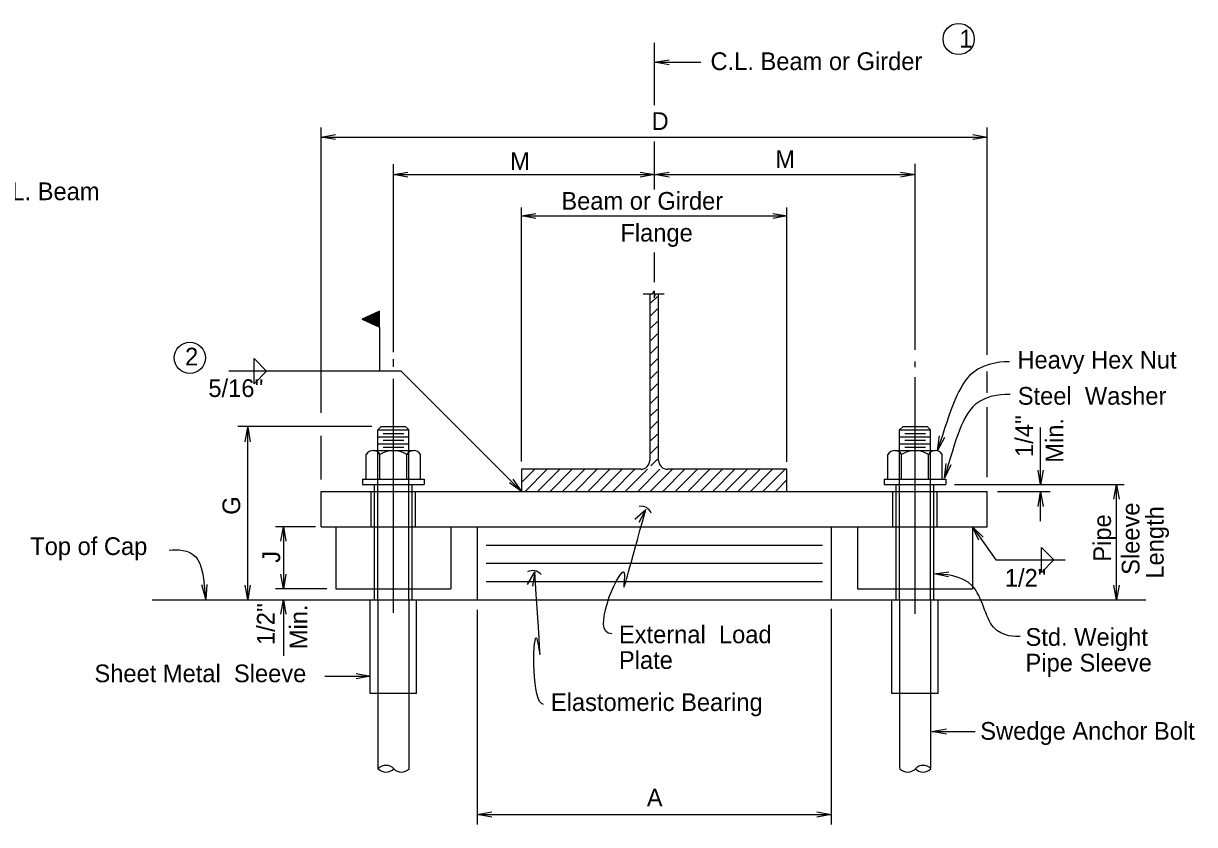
# Model space of a CAD drawing. Extents: x 113 to 232, y -103 to -27.
# Drawn here: x 123.95 to 129.46, y -71.71 to -67.93 of the extents above; entities that cross this region are included whole.
import ezdxf

# ---------------------------------------------------------------- set-up
doc = ezdxf.new("R2010")
doc.units = 0
doc.layers.add('1', color=7, linetype='Continuous')
doc.layers.add('B_Dimension', color=7, linetype='Continuous')

msp = doc.modelspace()

# ---------------------------------------------------------------- linework, layer by layer
at = {"layer": '1'}
for p, q in [((126.9201, -68.3191), (126.9201, -68.0268)), ((126.9201, -68.118), (127.1374, -68.118)), ((125.35, -69.7675), (125.35, -68.4251)), ((125.35, -68.4698), (128.4859, -68.4698)), ((128.4859, -69.4948), (128.4859, -68.4251)), ((126.9201, -68.717), (126.9201, -68.49)), ((125.69, -69.4816), (125.69, -68.5975)), ((128.1459, -69.4709), (128.1459, -68.5966)), ((125.69, -68.6466), (126.9201, -68.6466)), ((126.9201, -68.6466), (128.1459, -68.6466)), ((126.2929, -69.9965), (126.2929, -68.8018)), ((127.5429, -69.9989), (127.5429, -68.8018)), ((126.2929, -68.8413), (127.5444, -68.8413)), ((126.9201, -69.1529), (126.9201, -69.0125)), ((126.9098, -69.2073), (126.9177, -69.1932)), ((126.9177, -69.1932), (126.9177, -69.2263)), ((126.8663, -69.2073), (126.9098, -69.2073)), ((126.8972, -69.2073), (126.8972, -69.9915)), ((126.9177, -69.2263), (126.9239, -69.2073)), ((126.9239, -69.2073), (126.9642, -69.2073)), ((126.9387, -69.9915), (126.9387, -69.2073)), ((125.6244, -69.2896), (125.5434, -69.3274)), ((125.6244, -69.2896), (125.6244, -69.289)), ((125.6244, -69.365), (125.6244, -69.2896)), ((125.5434, -69.3274), (125.6244, -69.365)), ((125.6244, -69.365), (125.6244, -69.3955)), ((125.6244, -69.3955), (125.6244, -69.5718)), ((125.0345, -69.6308), (125.0345, -69.5128)), ((125.0345, -69.5128), (125.0935, -69.5718)), ((125.69, -69.5517), (125.69, -69.5157)), ((125.7274, -69.5718), (124.9152, -69.5718)), ((125.0935, -69.5718), (125.0345, -69.6308)), ((126.2929, -70.1374), (125.7274, -69.5718)), ((128.1459, -69.5532), (128.1459, -69.5258)), ((128.4859, -69.6732), (128.4859, -69.5735)), ((125.69, -70.7095), (125.69, -69.6072)), ((128.1459, -70.7145), (128.1459, -69.6003)), ((128.4859, -70.07), (128.4859, -69.7415)), ((125.5894, -69.832), (124.9581, -69.832)), ((125.0042, -70.6479), (125.0042, -69.8355)), ((125.6334, -69.832), (125.6171, -69.8483)), ((125.6171, -69.9455), (125.6171, -69.8483)), ((125.6171, -69.8483), (125.7629, -69.8483)), ((125.6334, -69.832), (125.7466, -69.832)), ((125.7466, -69.832), (125.7629, -69.8483)), ((125.7629, -69.9455), (125.7629, -69.8483)), ((128.073, -69.8483), (128.0893, -69.832)), ((128.073, -69.8483), (128.2188, -69.8483)), ((128.073, -69.9455), (128.073, -69.8483)), ((128.073, -69.8483), (128.2188, -69.8483)), ((128.0893, -69.832), (128.2025, -69.832)), ((128.2025, -69.832), (128.2188, -69.8483)), ((128.2188, -69.9455), (128.2188, -69.8483)), ((128.7372, -70.1065), (128.7372, -69.8375)), ((125.35, -70.0819), (125.35, -69.8759)), ((125.6171, -69.8807), (125.7629, -69.8807)), ((125.6414, -69.8646), (125.7386, -69.8646)), ((125.6414, -69.897), (125.7386, -69.897)), ((128.073, -69.8807), (128.2188, -69.8807)), ((128.0973, -69.8646), (128.1945, -69.8646)), ((128.0973, -69.897), (128.1945, -69.897)), ((125.5626, -70.0793), (125.5626, -69.9638)), ((125.5947, -69.9455), (125.7855, -69.9455)), ((125.6171, -69.913), (125.7629, -69.913)), ((125.6171, -70.6479), (125.6171, -69.9455)), ((125.627, -70.0793), (125.627, -69.9638)), ((125.6414, -69.9294), (125.7386, -69.9294)), ((125.7531, -70.0793), (125.7531, -69.9638)), ((125.7629, -70.6479), (125.7629, -69.9455)), ((125.8177, -70.0793), (125.8177, -69.9638)), ((128.0186, -70.0793), (128.0186, -69.9638)), ((128.0507, -69.9455), (128.2414, -69.9455)), ((128.073, -69.913), (128.2188, -69.913)), ((128.073, -70.6479), (128.073, -69.9455)), ((128.0829, -70.0793), (128.0829, -69.9638)), ((128.0973, -69.9294), (128.1945, -69.9294)), ((128.2091, -70.0793), (128.2091, -69.9638)), ((128.2188, -70.6479), (128.2188, -69.9455)), ((128.2737, -70.0793), (128.2737, -69.9638)), ((126.8555, -70.0332), (126.2929, -70.0332)), ((126.2929, -70.0332), (126.2929, -70.1374)), ((127.5429, -70.0332), (126.9804, -70.0332)), ((127.5429, -70.1374), (127.5429, -70.0332)), ((125.5441, -70.0793), (125.8358, -70.0793)), ((125.5441, -70.0793), (125.5441, -70.1053)), ((125.5441, -70.1053), (125.8358, -70.1053)), ((125.6015, -70.1386), (125.6015, -70.1056)), ((125.7785, -70.1386), (125.7785, -70.1056)), ((125.8358, -70.0793), (125.8358, -70.1053)), ((128.0001, -70.0793), (128.2917, -70.0793)), ((128.0001, -70.0793), (128.0001, -70.1053)), ((128.0001, -70.1053), (128.2917, -70.1053)), ((128.0574, -70.1382), (128.0574, -70.1049)), ((128.2344, -70.1382), (128.2344, -70.1059)), ((128.2917, -70.0793), (128.2917, -70.1053)), ((128.3317, -70.1053), (129.1305, -70.1053)), ((129.0945, -70.6479), (129.0945, -70.1053)), ((125.35, -70.304), (125.35, -70.1374)), ((125.35, -70.1374), (128.4859, -70.1374)), ((125.5859, -70.304), (125.5859, -70.1386)), ((125.6015, -70.304), (125.6015, -70.1386)), ((125.7785, -70.3039), (125.7785, -70.1386)), ((125.7941, -70.304), (125.7941, -70.1386)), ((128.0418, -70.305), (128.0418, -70.1382)), ((128.0574, -70.305), (128.0574, -70.1382)), ((128.2344, -70.306), (128.2344, -70.1412)), ((128.25, -70.306), (128.25, -70.1412)), ((128.4859, -70.304), (128.4859, -70.1374)), ((128.5338, -70.1374), (128.7828, -70.1374)), ((128.7372, -70.2774), (128.7372, -70.1398)), ((125.3235, -70.304), (125.1359, -70.304)), ((125.1721, -70.304), (125.1721, -70.5957)), ((125.35, -70.304), (128.4859, -70.304)), ((125.4192, -70.304), (125.4192, -70.5957)), ((125.6015, -70.5957), (125.6015, -70.304)), ((125.7785, -70.5957), (125.7785, -70.3039)), ((125.9608, -70.304), (125.9608, -70.5957)), ((126.0846, -70.304), (126.0846, -70.6479)), ((127.7513, -70.304), (127.7513, -70.6479)), ((127.8751, -70.304), (127.8751, -70.5957)), ((128.0574, -70.5957), (128.0574, -70.305)), ((128.2344, -70.5957), (128.2344, -70.306)), ((128.4167, -70.304), (128.4167, -70.5957)), ((128.4167, -70.304), (128.5267, -70.46)), ((126.1263, -70.39), (127.7096, -70.39)), ((128.7408, -70.519), (128.7408, -70.401)), ((128.7408, -70.401), (128.7998, -70.46)), ((128.5267, -70.46), (128.8531, -70.46)), ((128.7998, -70.46), (128.7408, -70.519)), ((126.1263, -70.476), (127.7096, -70.476)), ((126.1263, -70.562), (127.7096, -70.562)), ((125.3775, -70.5957), (125.1359, -70.5957)), ((125.4192, -70.5957), (125.9608, -70.5957)), ((125.6015, -70.6479), (125.6015, -70.5957)), ((125.7785, -70.6479), (125.7785, -70.5957)), ((127.8751, -70.5957), (128.4168, -70.5957)), ((128.0574, -70.6479), (128.0574, -70.5957)), ((128.2344, -70.6479), (128.2344, -70.5957)), ((124.5543, -70.6479), (129.2325, -70.6479)), ((125.1721, -70.6479), (125.1721, -70.9116)), ((125.5815, -71.0881), (125.5815, -70.6479)), ((125.6171, -70.6479), (125.6171, -71.0881)), ((125.7629, -70.6479), (125.7629, -71.0881)), ((125.7985, -71.0881), (125.7985, -70.6479)), ((128.0374, -71.0881), (128.0374, -70.6479)), ((128.073, -70.6479), (128.073, -71.0881)), ((128.2188, -70.6479), (128.2188, -71.0881)), ((128.2544, -71.0881), (128.2544, -70.6479)), ((126.0846, -70.6954), (126.0846, -71.7058)), ((127.7513, -70.6909), (127.7513, -71.7058)), ((125.3671, -71.0074), (125.583, -71.0074)), ((125.7985, -71.0881), (125.5815, -71.0881)), ((125.6171, -71.0881), (125.6171, -71.4447)), ((125.7629, -71.0881), (125.7629, -71.4445)), ((128.2544, -71.0881), (128.0374, -71.0881)), ((128.073, -71.0881), (128.073, -71.4412)), ((128.2188, -71.0881), (128.2188, -71.4414)), ((128.2257, -71.2679), (128.4284, -71.2679)), ((126.0846, -71.6581), (127.7513, -71.6581))]:
    msp.add_line(p, q, dxfattribs=at)
for points in [[(126.9024, -69.2507), (126.9335, -69.2195)], [(125.5961, -69.3519), (125.5961, -69.3029)], [(125.6003, -69.3538), (125.6003, -69.3009)], [(125.6046, -69.3558), (125.6046, -69.2989)], [(125.6089, -69.3578), (125.6089, -69.2969)], [(125.6132, -69.3599), (125.6132, -69.295)], [(125.6176, -69.3619), (125.6176, -69.2929)], [(125.6218, -69.3638), (125.6218, -69.2909)], [(126.9024, -69.3096), (126.9335, -69.2785)], [(125.5444, -69.3278), (125.5444, -69.327)], [(125.5486, -69.3299), (125.5486, -69.325)], [(125.553, -69.3319), (125.553, -69.323)], [(125.5573, -69.3338), (125.5573, -69.321)], [(125.5616, -69.3358), (125.5616, -69.319)], [(125.5659, -69.3378), (125.5659, -69.317)], [(125.5702, -69.3399), (125.5702, -69.315)], [(125.5745, -69.3419), (125.5745, -69.313)], [(125.5788, -69.3438), (125.5788, -69.311)], [(125.5831, -69.3458), (125.5831, -69.309)], [(125.5874, -69.3478), (125.5874, -69.307)], [(125.5917, -69.3499), (125.5917, -69.305)], [(126.9024, -69.3685), (126.9335, -69.3374)], [(126.9024, -69.4275), (126.9335, -69.3963)], [(126.9024, -69.4864), (126.9335, -69.4552)], [(126.9024, -69.5453), (126.9335, -69.5141)], [(126.9024, -69.6042), (126.9335, -69.573)], [(126.9024, -69.6631), (126.9335, -69.632)], [(126.9024, -69.722), (126.9335, -69.6909)], [(126.9024, -69.781), (126.9335, -69.7498)], [(126.9024, -69.8399), (126.9335, -69.8087)], [(126.9024, -69.8988), (126.9335, -69.8676)], [(126.9024, -69.9577), (126.9335, -69.9265)], [(126.9024, -70.0166), (126.9335, -69.9855)], [(126.2929, -70.0958), (126.3555, -70.0332)], [(126.2929, -70.0369), (126.2966, -70.0332)], [(126.3103, -70.1374), (126.4144, -70.0332)], [(126.3692, -70.1374), (126.4734, -70.0332)], [(126.4281, -70.1374), (126.5323, -70.0332)], [(126.487, -70.1374), (126.5912, -70.0332)], [(126.5459, -70.1374), (126.6501, -70.0332)], [(126.6049, -70.1374), (126.709, -70.0332)], [(126.6638, -70.1374), (126.7679, -70.0332)], [(126.7227, -70.1374), (126.8269, -70.0332)], [(126.7816, -70.1374), (126.8859, -70.0332)], [(126.8406, -70.1374), (126.9448, -70.0332)], [(126.8995, -70.1374), (127.0037, -70.0332)], [(126.9584, -70.1374), (127.0626, -70.0332)], [(127.0174, -70.1374), (127.1215, -70.0332)], [(127.0763, -70.1374), (127.1804, -70.0332)], [(127.1352, -70.1374), (127.2394, -70.0331)], [(127.1941, -70.1374), (127.2983, -70.0332)], [(127.2531, -70.1373), (127.3572, -70.0332)], [(127.3119, -70.1374), (127.4162, -70.0332)], [(127.3709, -70.1374), (127.4751, -70.0332)], [(127.4299, -70.1374), (127.534, -70.0332)], [(127.4888, -70.1374), (127.5429, -70.0832)], [(125.7007, -70.1374), (125.7007, -70.1374)], [(125.8186, -70.1374), (125.8186, -70.1374)], [(125.8776, -70.1374), (125.8776, -70.1374)], [(128.0393, -70.1374), (128.0393, -70.1374)], [(128.4463, -70.3669), (128.4167, -70.304), (128.466, -70.353)]]:
    msp.add_lwpolyline(points, dxfattribs=at)
for centre in [(128.3514, -68.0083), (124.7318, -69.509)]:
    msp.add_circle(centre, 0.0733, dxfattribs=at)
for centre, radius, start, end in [((125.5948, -69.9829), 0.0375, 30.8086, 149.1914), ((125.6901, -70.0635), 0.118, 57.6898, 122.3102), ((125.7855, -69.9831), 0.0376, 30.9573, 149.0427), ((128.0507, -69.9829), 0.0375, 30.8086, 149.1914), ((128.146, -70.0635), 0.118, 57.6898, 122.3102), ((128.2414, -69.9831), 0.0376, 30.9573, 149.0427), ((126.8555, -69.9915), 0.0417, 270, 360), ((126.9804, -69.9915), 0.0417, 180, 270), ((126.8565, -70.2589), 0.0513, 21.6992, 99.9226), ((126.3465, -70.5617), 0.0513, 40.3962, 118.6196), ((125.6551, -71.4778), 0.0504, 43.7135, 136.2865), ((125.6551, -71.4081), 0.0504, 223.7135, 316.2865), ((125.728, -71.4081), 0.0504, 223.7135, 316.2865), ((128.111, -71.4081), 0.0504, 223.7135, 316.2865), ((128.184, -71.4778), 0.0504, 43.7135, 136.2865), ((128.184, -71.4081), 0.0504, 223.7135, 316.2865)]:
    msp.add_arc(centre, radius, start, end, dxfattribs=at)
for points in [[(128.5908, -69.5282), (128.5741, -69.5276), (128.387, -69.5246), (128.3162, -69.7447), (128.2516, -69.9454)], [(128.594, -69.6821), (128.5776, -69.6815), (128.4003, -69.6749), (128.3392, -69.884), (128.2848, -70.0756)], [(126.7179, -70.8083), (126.6159, -70.8083), (126.8782, -70.2226), (126.7179, -70.8083), (126.8782, -70.2226)], [(124.6353, -70.4135), (124.6708, -70.4108), (124.7847, -70.4114), (124.7976, -70.5479), (124.8066, -70.6446)], [(126.3975, -71.1404), (126.3393, -71.1369), (126.3557, -70.5158), (126.3975, -71.1404), (126.3557, -70.5158)], [(128.6413, -70.82), (128.6245, -70.8212), (128.4869, -70.8273), (128.4519, -70.5348), (128.2815, -70.5275), (128.2362, -70.5255)]]:
    msp.add_open_spline(points, degree=3, dxfattribs=at)
at = {"layer": 'B_Dimension'}
for points in [[(126.9884, -68.13), (126.9201, -68.118), (126.9884, -68.1059)], [(125.4183, -68.4819), (125.35, -68.4698), (125.4183, -68.4578)], [(128.4176, -68.4578), (128.4859, -68.4698), (128.4176, -68.4819)], [(125.7583, -68.6586), (125.69, -68.6466), (125.7583, -68.6345)], [(126.8518, -68.6345), (126.9201, -68.6466), (126.8518, -68.6586)], [(126.9884, -68.6586), (126.9201, -68.6466), (126.9884, -68.6345)], [(128.0776, -68.6345), (128.1459, -68.6466), (128.0776, -68.6586)], [(126.3613, -68.8533), (126.2929, -68.8413), (126.3613, -68.8292)], [(127.476, -68.8292), (127.5444, -68.8413), (127.476, -68.8533)], [(124.9922, -69.9039), (125.0042, -69.8355), (125.0163, -69.9039)], [(128.284, -69.8841), (128.2516, -69.9454), (128.2611, -69.8767)], [(128.3151, -70.0131), (128.2848, -70.0756), (128.2919, -70.0066)], [(128.7493, -70.0381), (128.7372, -70.1065), (128.7252, -70.0381)], [(126.2531, -70.0805), (126.2929, -70.1374), (126.2361, -70.0976)], [(129.0825, -70.1736), (129.0945, -70.1053), (129.1066, -70.1736)], [(128.7252, -70.2081), (128.7372, -70.1398), (128.7493, -70.2081)], [(126.8268, -70.2691), (126.8782, -70.2226), (126.8458, -70.2839)], [(125.16, -70.3724), (125.1721, -70.304), (125.1841, -70.3724)], [(126.322, -70.5764), (126.3557, -70.5158), (126.3448, -70.5843)], [(128.304, -70.5405), (128.2362, -70.5255), (128.305, -70.5164)], [(125.1841, -70.5274), (125.1721, -70.5957), (125.16, -70.5274)], [(124.8122, -70.5755), (124.8066, -70.6446), (124.7883, -70.5777)], [(125.0163, -70.5796), (125.0042, -70.6479), (124.9922, -70.5796)], [(129.1066, -70.5796), (129.0945, -70.6479), (129.0825, -70.5796)], [(125.16, -70.7162), (125.1721, -70.6479), (125.1841, -70.7162)], [(125.5147, -70.9954), (125.583, -71.0074), (125.5147, -71.0195)], [(128.294, -71.2799), (128.2257, -71.2679), (128.294, -71.2558)], [(126.1529, -71.6702), (126.0846, -71.6581), (126.1529, -71.6461)], [(127.683, -71.6461), (127.7513, -71.6581), (127.683, -71.6702)]]:
    msp.add_lwpolyline(points, dxfattribs=at)

# ---------------------------------------------------------------- texts
at = {"layer": '1'}
for s, height, p in [('1', 0.0833, (128.3545, -68.0483)), ('C.L. Beam or Girder', 0.083334, (127.1831, -68.1545)), ('D', 0.0833, (126.9056, -68.4363)), ('M', 0.0833, (126.2395, -68.6247)), ('M', 0.0833, (127.488, -68.6156)), ('C.L Elastomeric Pad shal l  be aligned with C.L. Beam', 0.083334, (121.6372, -68.7669)), ('Beam or Girder', 0.083334, (126.4809, -68.8118)), ('Flange', 0.08333, (126.7589, -68.9618)), ('2', 0.0833, (124.7097, -69.5447)), ('Heavy Hex Nut', 0.083334, (128.6279, -69.5597)), ("5/16''", 0.08333, (124.8193, -69.6932)), ('Steel  Washer', 0.083334, (128.6295, -69.7297)), ('Top of Cap', 0.08333, (123.9806, -70.437)), ('1/2"', 0.08333, (128.5687, -70.586)), ('External  Load ', 0.083334, (126.752, -70.8522)), ('Std. Weight ', 0.083334, (128.6661, -70.8645)), ('Plate', 0.08333, (126.752, -70.973)), ('Pipe Sleeve', 0.083334, (128.6661, -70.9854)), ('Sheet Metal  Sleeve', 0.083334, (124.2829, -71.0358)), ('Elastomeric Bearing', 0.083334, (126.4316, -71.1712)), ('Swedge Anchor Bolt', 0.083334, (128.453, -71.3065)), ('A', 0.0833, (126.8832, -71.6206))]:
    msp.add_text(s, height=height, dxfattribs=at).set_placement(p)
for s, height, p in [("1/4''", 0.08333, (128.7018, -69.9758)), ('Min.', 0.08333, (128.8442, -70.0028)), ('G', 0.0833, (124.9689, -70.2477)), ('Sleeve ', 0.08333, (129.2025, -70.5305)), ('Length', 0.08333, (129.3164, -70.5482)), ('Pipe', 0.08333, (129.0685, -70.4684)), ('J', 0.0833, (125.1573, -70.4737)), ("1/2''", 0.08333, (125.131, -70.8605)), ('Min.', 0.08333, (125.2857, -70.8802))]:
    msp.add_text(s, height=height, rotation=90, dxfattribs=at).set_placement(p)

doc.saveas('drawing.dxf')
